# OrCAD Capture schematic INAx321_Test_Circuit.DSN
size A; title: INA321, microPower, Single-Supply, CMOS; rev: 1.1; note: Datasheet : SBOS168D EVM : NA; note: Reference
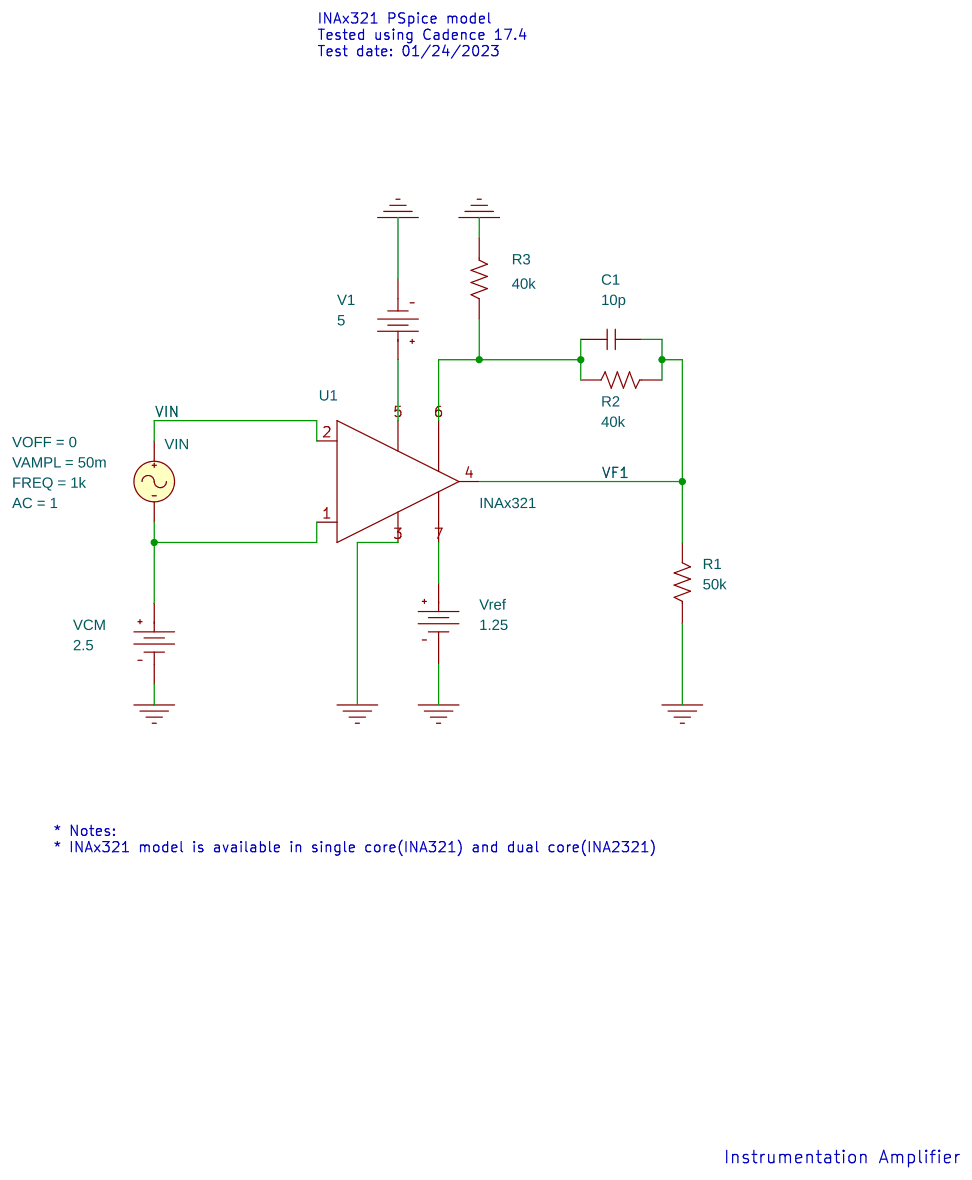
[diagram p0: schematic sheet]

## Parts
C1  10p  [RAD/CK05]
R1  50k  [AX/RC05]
R2  40k  [AX/RC05]
R3  40k  [AX/RC05]
U1  INAx321
V1  VDC
VCM  VDC
VIN  VSIN
Vref  VDC

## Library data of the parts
C1 = C
R1-R3 = R
U1 = INAx321
V1 = VDC: DC: 5
VCM = VDC: DC: 2.5
VIN = VSIN: AC: 1; FREQ: 1k; VAMPL: 50m; VOFF: 0
Vref = VDC: DC: 1.25

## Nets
VIN: U1.2(-) VIN.1(+)
0: R1.1 R3.1 U1.3(V-) V1.1(-) VCM.1(-) Vref.1(-)
VF1: C1.2 R1.2 R2.1 U1.4(OUT)
N01574: U1.1(+) VCM.0(+) VIN.2(-)
N14287329: C1.1 R2.2 R3.2 U1.6(RG)
N14288518: U1.7(REF) Vref.0(+)
N14292365: U1.5(V+) V1.0(+)

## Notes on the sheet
- INAx321 PSpice model
  Tested using Cadence 17.4
  Test date: 01/24/2023
- * Notes:
  * INAx321 model is available in single core(INA321) and dual core(INA2321)
- Instrumentation Amplifier
